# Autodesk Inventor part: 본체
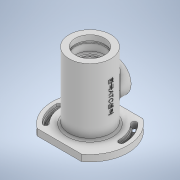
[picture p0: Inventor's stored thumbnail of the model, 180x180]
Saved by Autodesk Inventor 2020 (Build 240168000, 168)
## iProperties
Created: 2022-05
Part Number: 본체
Material: 일반
Document SubType Name: Modeling
Designer: Student
Density: 1 g/cm^3
Appearance: 기본값
Author: Student
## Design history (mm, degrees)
sketch "스케치5"
  geometry: L1 (33.985, -47)-(-33.985, -47); L2 (-33.985, 47)-(33.985, 47); A1 r 58 centre (0, 0) between (33.985, -47) and (33.985, 47); A2 r 58 centre (0, 0) between (-33.985, 47) and (-33.985, -47); 1 further point
  constraints: 4 end point, 4 point on circle, 2 centre point, 1 coincident, 1 concentric, 1 horizontal, 1 parallel
  dimensions: "d62" = 58 radius of A2; "d63" = 94 distance between parallel lines of L1 L2; "d64" = 47 distance from line of L2 point (0, 0)
extrude "돌출1" new body sketch "스케치5" distance "d65" = 10; taper "d66" = 0 deg
sketch "스케치6"
  geometry: C1 r 36 at (0, 0); 1 further point
  constraints: 1 centre point, 1 coincident
  dimensions: "d67" = 36 radius of C1
extrude "돌출2" join sketch "스케치6" distance "d68" = 3; taper "d69" = 0 deg
sketch "스케치8"
  geometry: C1 r 32 at (0, 0); 1 further point
  constraints: 1 centre point, 1 coincident
  dimensions: "d70" = 64 diameter of C1
extrude "돌출3" join sketch "스케치8" distance "d71" = 102; taper "d72" = 0 deg
sketch "스케치10"
  geometry: L1 (112, -22.5)-(104, -22.5); L2 (112, -32)-(112, 32) reference; L3 (104, -22.5)-(104, -24); L4 (104, -24)-(101, -24); L5 (101, -24)-(101, -22.5); L6 (101, -22.5)-(90, -22.5); L7 (90, -22.5)-(90, -17.5); L8 (90, -17.5)-(87.75, -17.5); L9 (87.75, -17.5)-(87.75, -18.5); L10 (87.75, -18.5)-(86, -18.5); L11 (86, -18.5)-(86, -17.5); L12 (86, -17.5)-(75, -17.5); L13 (75, -17.5)-(75, -27); L14 (0, 0)-(159.054, 0); L15 (75, -27)-(37, -27); L16 (37, -27)-(37, -20); L17 (37, -20)-(26, -20); L18 (26, -20)-(26, -15); L19 (26, -15)-(21, -15); L20 (21, -15)-(21, -11); L21 (21, -11)-(17.3, -11); L22 (17.3, -11)-(17.3, -15); L23 (17.3, -15)-(10, -15); L24 (10, -15)-(10, -20); L25 (10, -20)-(-3, -30); L26 (112, -22.5)-(112, 0); L27 (-3, 0)-(112, 0); L28 (-3, 36)-(-3, -36) reference; L29 (-3, -30)-(-3, 0); 1 further point
  constraints: 54 end point, 15 perpendicular, 8 point on line, 4 horizontal, 2 vertical, 1 collinear, 1 midpoint, 1 parallel
  dimensions: "d79" = 8 distance between parallel lines of L3 L2; "d80" = 3 distance of L3.end L4.end; "d82" = 22 distance between parallel lines of L7 L2; "d83" = 11 distance of L11.end L12.end; "d84" = 1.75 distance of L9.end L10.end; "d85" = 37 diameter of L10 L14; "d86" = 45 diameter of L1 L14; "d87" = 48 diameter of L4 L14; "d88" = 45 diameter of L6 L14; "d89" = 35 diameter of L8 L14; "d90" = 4 distance between parallel lines of L7 L11; "d91" = 38 distance of L13.end L15.end; "d92" = 11 distance between parallel lines of L18 L16; "d93" = 5 distance of L18.end L19.end; "d95" = 60 diameter of L25.end L14; "d96" = 40 diameter of L24.end L14; "d97" = 30 diameter of L23 L14; "d98" = 22 diameter of L21 L14; "d99" = 7.3 distance between parallel lines of L22 L24; "d100" = 54 diameter of L15 L14; "d102" = 47.0541 distance from line of L14.end L2; "d105" = 13 distance between parallel lines of L24 L28
revolve "회전1" sketch "스케치10" stored, may be unused: angle "d104" = 90 deg
fillet "모깎기1" dims "d106" = 0.5
sketch "스케치11"
  geometry: L1 (0, 0)-(48, 0); L2 (0, 0)-(33.941, 33.941); L3 (0, 0)-(70.158, 0); C1 r 14.5 at (0, 0) reference; A1 r 48 centre (0, 0) between (48, 0) and (33.941, 33.941); A2 r 52 centre (0, 0) between (52, 0) and (36.77, 36.77); A3 r 44 centre (0, 0) between (44, 0) and (31.113, 31.113); A4 r 4 centre (48, 0) between (44, 0) and (52, 0); A5 r 4 centre (33.941, 33.941) between (36.77, 36.77) and (31.113, 31.113); 1 further point
  constraints: 10 point on circle, 6 end point, 5 centre point, 4 tangent, 1 coincident, 1 horizontal, 1 point on line
  dimensions: "d107" = 4 radius of A4; "d108" = 48 radius of A1; "d109" = 45 deg angle of L1 L2
extrude "돌출4" cut sketch "스케치11" distance "d110" = 4.4; taper "d111" = 0 deg
sketch "스케치12"
  geometry: A1 r 4 centre (33.941, 33.941) between (36.77, 36.77) and (31.113, 31.113) reference; A2 r 4 centre (48, 0) between (44, 0) and (52, 0) reference; A3 r 48 centre (0, 0) between (48, 0) and (33.941, 33.941); A4 r 50.25 centre (0, 0) between (50.25, 0) and (35.532, 35.532); A5 r 45.75 centre (0, 0) between (45.75, 0) and (32.35, 32.35); A6 r 2.25 centre (48, 0) between (45.75, 0) and (50.25, 0); A7 r 2.25 centre (33.941, 33.941) between (35.532, 35.532) and (32.35, 32.35); 1 further point
  constraints: 10 point on circle, 5 centre point, 4 tangent, 1 coincident
  dimensions: "d112" = 4.5 diameter of A6
extrude "돌출5" cut sketch "스케치12" distance "d113" = 4.4; taper "d114" = 0 deg
sketch "스케치13"
  geometry: C1 r 4 at (33.941, 33.941); A1 r 50.25 centre (0, 0) between (50.25, 0) and (35.532, 35.532) reference; A2 r 2.25 centre (33.941, 33.941) between (35.532, 35.532) and (32.35, 32.35) reference; A3 r 45.75 centre (0, 0) between (45.75, 0) and (32.35, 32.35) reference; A4 r 2.25 centre (48, 0) between (45.75, 0) and (50.25, 0) reference; 1 further point
  constraints: 1 centre point, 1 coincident
  dimensions: "d115" = 8 diameter of C1
extrude "돌출6" cut sketch "스케치13" extent not by distance; stored distance "d116" = 4.4; taper "d117" = 0 deg
node "작업 평면1"
sketch "스케치14"
  geometry: L1 (32, 112)-(-32, 112) reference; L2 (33.985, 0)-(-33.985, 0) reference; C1 r 25 at (0, 56); 2 further points
  constraints: 1 centre point, 1 midpoint, 1 vertical alignment
  dimensions: "d122" = 50 diameter of C1; "d123" = 56 distance from line of C1.centre L1
extrude "돌출7" join sketch "스케치14" stored distance "d124" = 4.4; taper "d125" = 0 deg
sketch "스케치15"
  geometry: C1 r 25 at (0, 56) reference; C2 r 16 at (0, 56); 1 further point
  constraints: 1 centre point, 1 coincident
  dimensions: "d126" = 32 diameter of C2
extrude "돌출9" cut sketch "스케치15" stored distance "d129" = 4.4; taper "d130" = 0 deg
sketch "스케치16"
  geometry: C1 r 16 at (0, 0) reference; 2 further points
  constraints: 1 horizontal alignment
  dimensions: "d131" = 20.5 distance of point (20.5, 0) C1.centre
hole "구멍1" sketch "스케치16" at (20.5, 0) diameter "d132" = 2.459; stored, may be unused: countersink angle "d136" = 90 deg, drill point angle "d138" = 118 deg; dims "d133" = 6, "d134" = 28, "d135" = 4, "d137" = 8
fillet "모깎기2" dims "d142" = 3
chamfer "모따기1" distance "d143" = 1; stored, may be unused: second distance "d144" = 2, angle "d145" = 30 deg
fillet "모깎기3" dims "d146" = 3
node "작업 평면2"
sketch "스케치17"
  geometry: L1 (0, -47)-(0, 47) reference; 2 further points
  constraints: 1 horizontal alignment, 1 other
  dimensions: "d148" = 62 distance from line of L1 point (62, 0)
feature "엠보싱1" sketch "스케치17" dims "d62" = 58, "d63" = 94, "d64" = 47, "d149" = 0.5, "d150" = 0
node "솔리드1"
pattern_circular "원형 패턴1" dims angle "d119" = 360 deg
pattern_circular "원형 패턴2" dims angle "d140" = 360 deg
node "투영된 루프1"
feature "A9D066F2-1C7D-4E18-AEED-F7BC21143FA4" dims "d132" = 2.459, "d133" = 6, "d134" = 28, "d135" = 4, "d136" = 90 deg, "d137" = 8, "d138" = 118 deg
other parameters: "d16" = 4, "d56" = 58, "d61" = 58, "d121" = -38, "d147" = 89
